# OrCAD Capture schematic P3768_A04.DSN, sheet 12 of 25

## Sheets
12 0013_USB Type C: size Custom
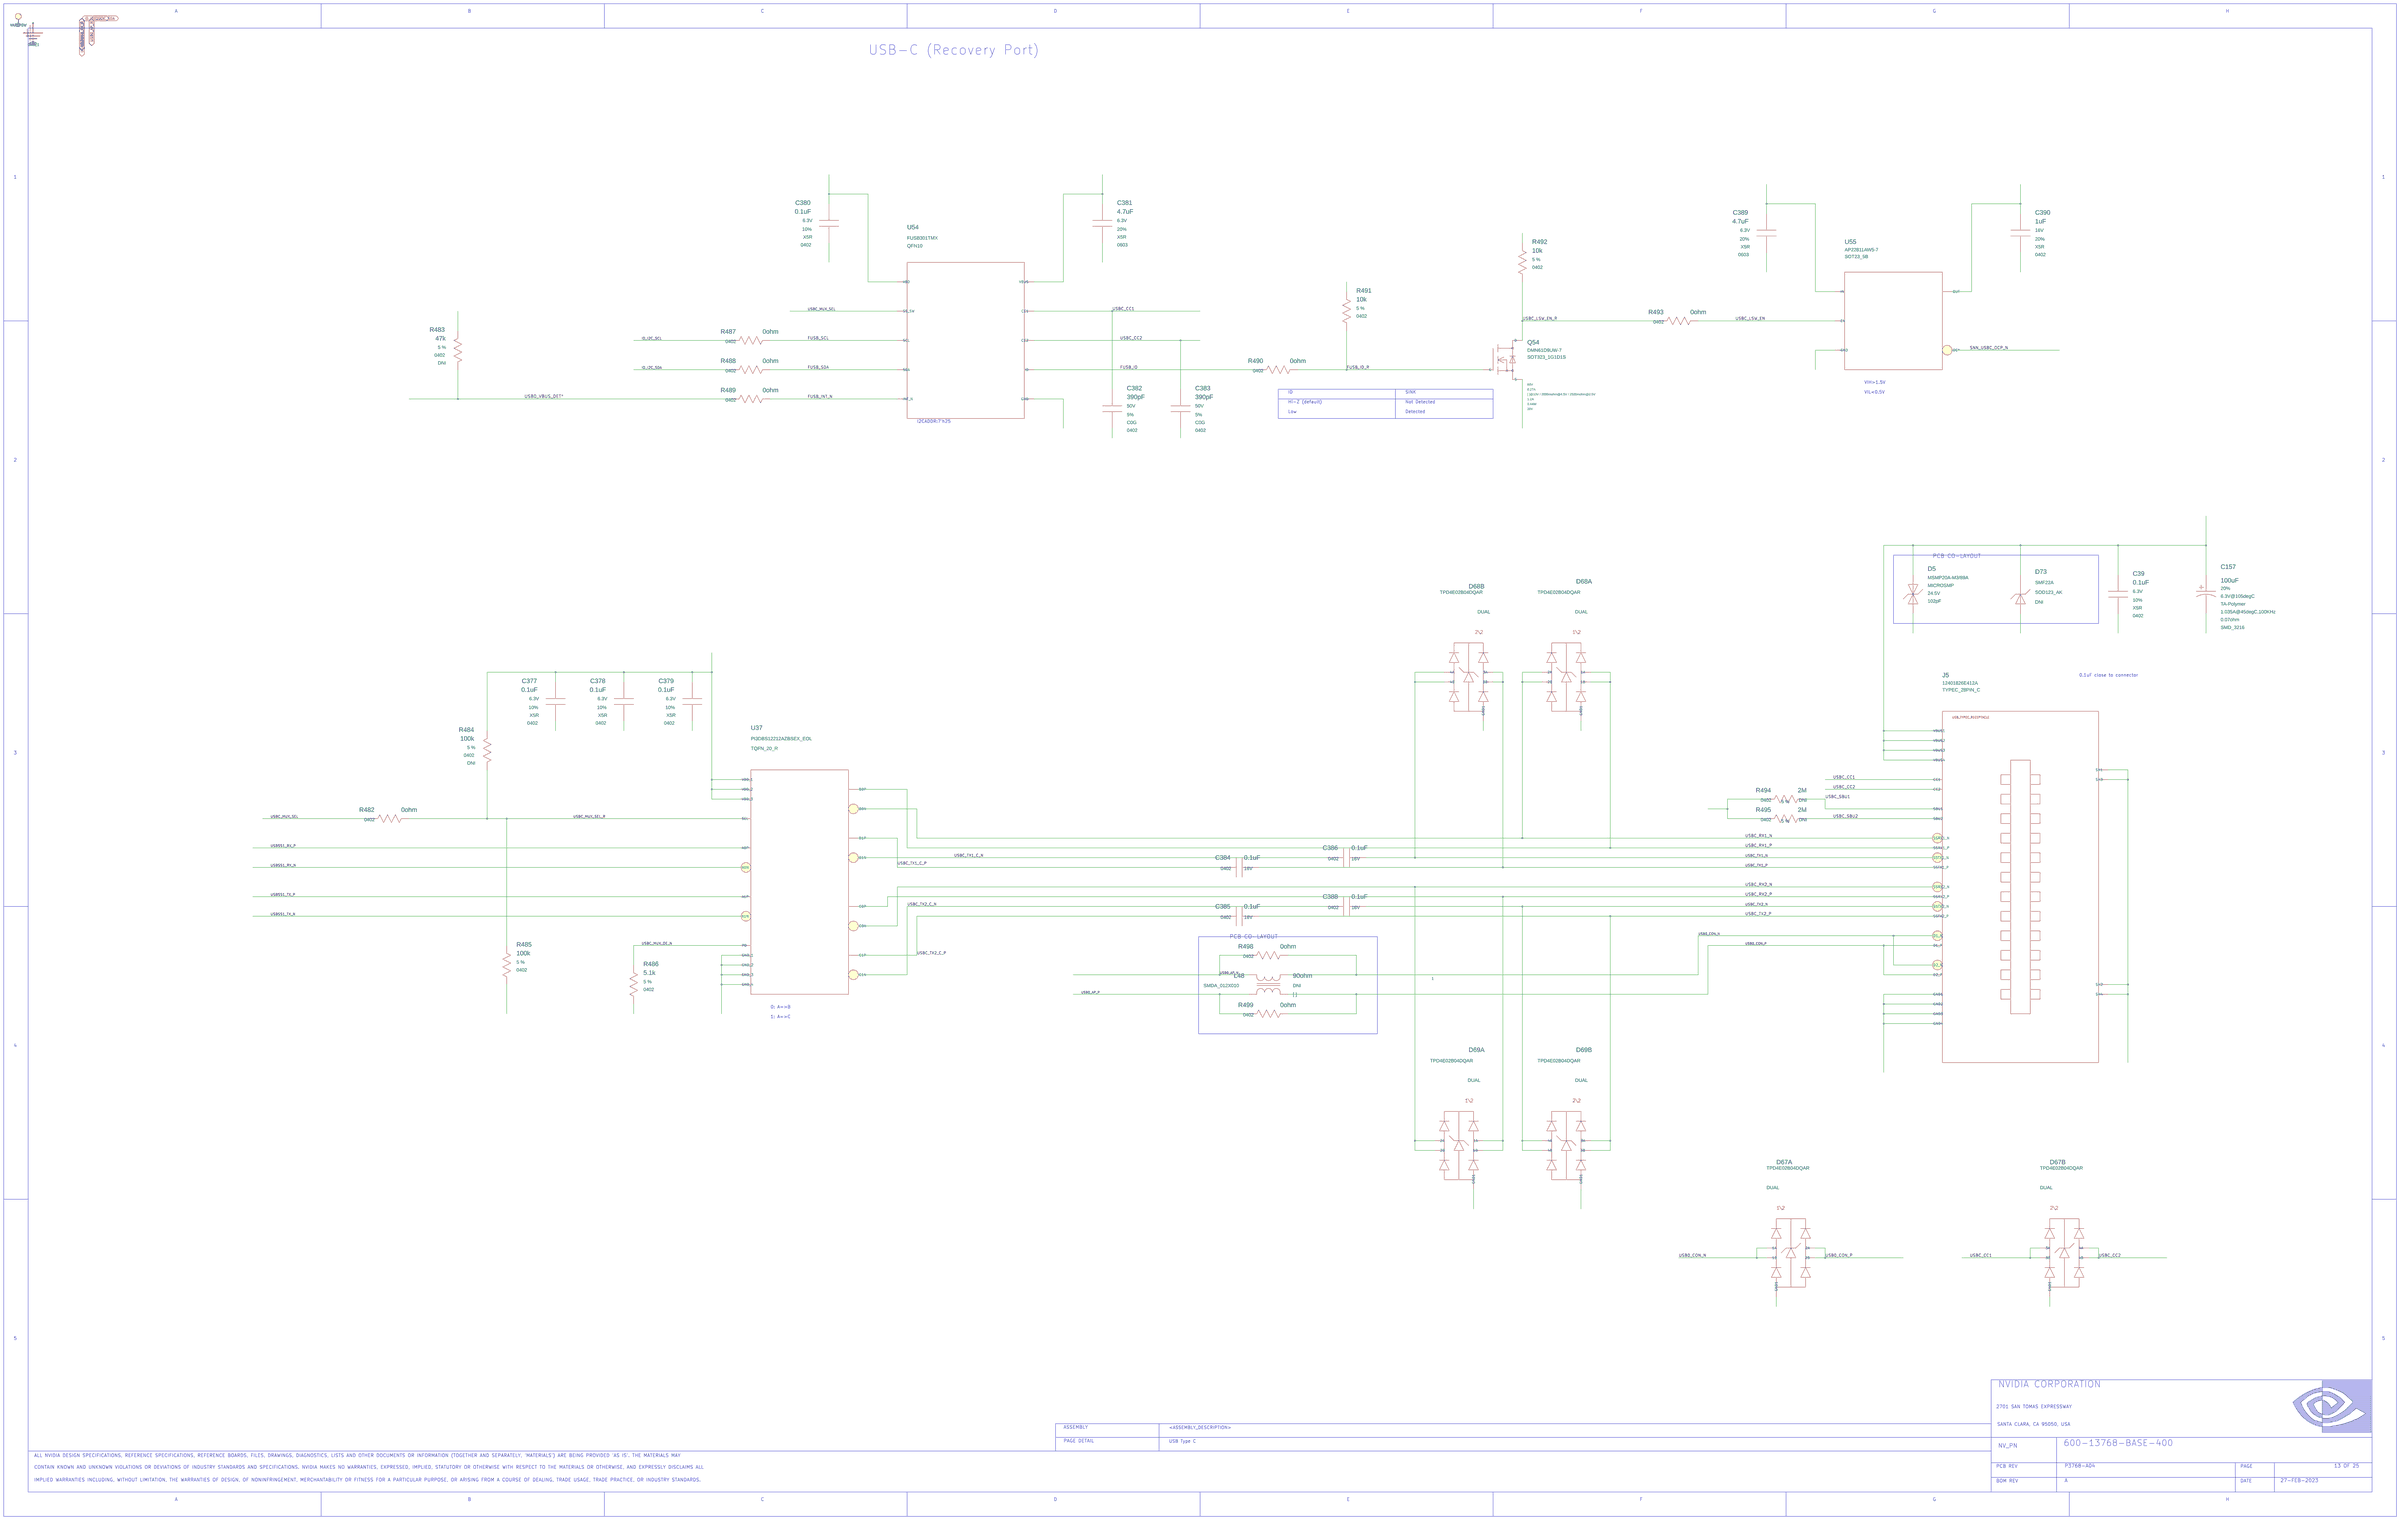
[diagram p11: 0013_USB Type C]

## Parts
C39  0.1uF  [0402]
C157  100uF  [CAP_SMD_3216]
C377  0.1uF  [0402]
C378  0.1uF  [0402]
C379  0.1uF  [0402]
C380  0.1uF  [0402]
C381  4.7uF  [0603]
C382  390pF  [0402]
C383  390pF  [0402]
C384  0.1uF  [0402]
C385  0.1uF  [0402]
C386  0.1uF  [0402]
C388  0.1uF  [0402]
C389  4.7uF  [0603]
C390  1uF  [0402]
D5  D_ESD  [DIODE_SMD_025X013]
D67  D_ESD_DIFFPAIR  [TSLP10_P050_025X010]  (sections A,B)
D68  D_ESD_DIFFPAIR  [TSLP10_P050_025X010]  (sections A,B)
D69  D_ESD_DIFFPAIR  [TSLP10_P050_025X010]  (sections A,B)
D73  D_ESD  [DIODE_SMD_SOD123_B_AKP]
J5  CON_USB3  [CON_USB_024_SMT_RA_F_100X096_C]
L48  90ohm  [IND_NONRKO_SMD_012X010]
Q54  Q_FET_N_ENH  [SOT323]
R482  0ohm  [0402]
R483  47k  [0402]
R484  100k  [0402]
R485  100k  [0402]
R486  5.1k  [0402]
R487  0ohm  [0402]
R488  0ohm  [0402]
R489  0ohm  [0402]
R490  0ohm  [0402]
R491  10k  [0402]
R492  10k  [0402]
R493  0ohm  [0402]
R494  2M  [0402]
R495  2M  [0402]
R498  0ohm  [0402]
R499  0ohm  [0402]
U37  U_MUX_PCIE  [MULTI_QFN020R_P050_0025X0045_T010X030]
U54  U_USB_FUSB301  [QFN010R_P040_0012X0016_B]
U55  U_SW_LOAD  [SOT23_5_B]

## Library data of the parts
C39 = C#1: ASSEMBLY: USBC; CDS_LIB: discrete; CDS_PART_NAME: C_0402-0.1UF,X5R,10%,6.3V,039-0007-000; CDS_PHYS_PART_NAME: C_0402-0.1UF,X5R,10%,6.3V,039-0007-000-0.1UF,039-0007-000; CDS_SEC: 1; CHIPS_PART_NAME: C; DEVICE_TYPENAME: C_0402-01UFX5R1063V039-0007-000-01UF039-0007-000; DRAWING: @P3768_A04_LIB.P3768_A04(SCH_1):PAGE13; MAT: X5R; MAX_VOLTAGE: 6.3V; NV_PN: 039-0007-000; PATH: I449; PHYS_PAGE: 13; ROT: 0; SEC: 1; SIGNAL_MODEL: nv_cap; TOL: 10%; VER: 1; XY: (-1300,4600)
C157 = C_POL: ASSEMBLY: USBC; CDS_LIB: discrete; CDS_PART_NAME: C_POL_SMD_3216-100UF,TA-POLYMER,20%,6.3V@105DEGC,0.07OHM,9.999UH,1.035A@45DEGC,100KHZ,032-0637-000; CDS_PHYS_PART_NAME: C_POL_SMD_3216-100UF,TA-POLYMER,20%,6.3V@105DEGC,0.07OHM,9.999UH,1.035A@45DEGC,100KHZ,032-0637-000-032-0637-000,100UF; CDS_SEC: 1; DEVICE_TYPENAME: C_POL_SMD_3216-100UFTA-POLYMER2063V105DEGC007OHM9999UH1035A45DEGC100KHZ032-0637-000-032-0637-000100UF; DRAWING: @P3768_A04_LIB.P3768_A04(SCH_1):PAGE13; ESL: 9.999uH; ESR: 0.07ohm; MAT: TA-Polymer; MAX_VOLTAGE: 6.3V@105degC; NV_PN: 032-0637-000; PACK_TYPE: SMD_3216; PATH: I467; PHYS_PAGE: 13; RIPPLE_CURRENT: 1.035A@45degC,100KHz; ROT: 0; SEC: 1; SIGNAL_MODEL: nv_capp; TOL: 20%; VER: 1; XY: (-850,4600)
C377 = C#1: ASSEMBLY: USBC; CDS_LIB: discrete; CDS_PART_NAME: C_0402-0.1UF,X5R,10%,6.3V,039-0007-000; CDS_PHYS_PART_NAME: C_0402-0.1UF,X5R,10%,6.3V,039-0007-000-0.1UF,039-0007-000; CDS_SEC: 1; CHIPS_PART_NAME: C; DEVICE_TYPENAME: C_0402-01UFX5R1063V039-0007-000-01UF039-0007-000; DRAWING: @P3768_A04_LIB.P3768_A04(SCH_1):PAGE13; MAT: X5R; MAX_VOLTAGE: 6.3V; NV_PN: 039-0007-000; PATH: I448; PHYS_PAGE: 13; ROT: 2; SEC: 1; SIGNAL_MODEL: nv_cap; TOL: 10%; VER: 1; XY: (-9300,4050)
C378 = C#1: ASSEMBLY: USBC; CDS_LIB: discrete; CDS_PART_NAME: C_0402-0.1UF,X5R,10%,6.3V,039-0007-000; CDS_PHYS_PART_NAME: C_0402-0.1UF,X5R,10%,6.3V,039-0007-000-0.1UF,039-0007-000; CDS_SEC: 1; CHIPS_PART_NAME: C; DEVICE_TYPENAME: C_0402-01UFX5R1063V039-0007-000-01UF039-0007-000; DRAWING: @P3768_A04_LIB.P3768_A04(SCH_1):PAGE13; MAT: X5R; MAX_VOLTAGE: 6.3V; NV_PN: 039-0007-000; PATH: I447; PHYS_PAGE: 13; ROT: 2; SEC: 1; SIGNAL_MODEL: nv_cap; TOL: 10%; VER: 1; XY: (-8950,4050)
C379 = C#1: ASSEMBLY: USBC; CDS_LIB: discrete; CDS_PART_NAME: C_0402-0.1UF,X5R,10%,6.3V,039-0007-000; CDS_PHYS_PART_NAME: C_0402-0.1UF,X5R,10%,6.3V,039-0007-000-0.1UF,039-0007-000; CDS_SEC: 1; CHIPS_PART_NAME: C; DEVICE_TYPENAME: C_0402-01UFX5R1063V039-0007-000-01UF039-0007-000; DRAWING: @P3768_A04_LIB.P3768_A04(SCH_1):PAGE13; MAT: X5R; MAX_VOLTAGE: 6.3V; NV_PN: 039-0007-000; PATH: I443; PHYS_PAGE: 13; ROT: 2; SEC: 1; SIGNAL_MODEL: nv_cap; TOL: 10%; VER: 1; XY: (-8600,4050)
C380 = C#1: ASSEMBLY: USBC; CDS_LIB: discrete; CDS_PART_NAME: C_0402-0.1UF,X5R,10%,6.3V,039-0007-000; CDS_PHYS_PART_NAME: C_0402-0.1UF,X5R,10%,6.3V,039-0007-000-0.1UF,039-0007-000; CDS_SEC: 1; CHIPS_PART_NAME: C; DEVICE_TYPENAME: C_0402-01UFX5R1063V039-0007-000-01UF039-0007-000; DRAWING: @P3768_A04_LIB.P3768_A04(SCH_1):PAGE13; MAT: X5R; MAX_VOLTAGE: 6.3V; NV_PN: 039-0007-000; PATH: I444; PHYS_PAGE: 13; ROT: 2; SEC: 1; SIGNAL_MODEL: nv_cap; TOL: 10%; VER: 1; XY: (-7900,6500)
C381 = C#1: ASSEMBLY: USBC; CDS_LIB: discrete; CDS_PART_NAME: C_0603-4.7UF,X5R,20%,6.3V,032-2124-000; CDS_PHYS_PART_NAME: C_0603-4.7UF,X5R,20%,6.3V,032-2124-000-032-2124-000,4.7UF; CDS_SEC: 1; CHIPS_PART_NAME: C; DEVICE_TYPENAME: C_0603-47UFX5R2063V032-2124-000-032-2124-00047UF; DRAWING: @P3768_A04_LIB.P3768_A04(SCH_1):PAGE13; MAT: X5R; MAX_VOLTAGE: 6.3V; NV_PN: 032-2124-000; PATH: I435; PHYS_PAGE: 13; ROT: 0; SEC: 1; SIGNAL_MODEL: nv_cap; TOL: 20%; VER: 1; XY: (-6500,6500)
C382 = C#1: ASSEMBLY: USBC; CDS_LIB: discrete; CDS_PART_NAME: C_0402-390PF,C0G,5%,50V,035-0293-000; CDS_PHYS_PART_NAME: C_0402-390PF,C0G,5%,50V,035-0293-000-035-0293-000,390PF; CDS_SEC: 1; CHIPS_PART_NAME: C; DEVICE_TYPENAME: C_0402-390PFC0G550V035-0293-000-035-0293-000390PF; DRAWING: @P3768_A04_LIB.P3768_A04(SCH_1):PAGE13; MAT: C0G; MAX_VOLTAGE: 50V; NV_PN: 035-0293-000; PATH: I410; PHYS_PAGE: 13; PSPICETEMPLATE: X^@REFDES  %1    %2   @NV_PN; ROT: 0; SEC: 1; SIGNAL_MODEL: nv_cap; TOL: 5%; VER: 1; XY: (-6450,5550)
C383 = C#1: ASSEMBLY: USBC; CDS_LIB: discrete; CDS_PART_NAME: C_0402-390PF,C0G,5%,50V,035-0293-000; CDS_PHYS_PART_NAME: C_0402-390PF,C0G,5%,50V,035-0293-000-035-0293-000,390PF; CDS_SEC: 1; CHIPS_PART_NAME: C; DEVICE_TYPENAME: C_0402-390PFC0G550V035-0293-000-035-0293-000390PF; DRAWING: @P3768_A04_LIB.P3768_A04(SCH_1):PAGE13; MAT: C0G; MAX_VOLTAGE: 50V; NV_PN: 035-0293-000; PATH: I414; PHYS_PAGE: 13; PSPICETEMPLATE: X^@REFDES  %1    %2   @NV_PN; ROT: 0; SEC: 1; SIGNAL_MODEL: nv_cap; TOL: 5%; VER: 1; XY: (-6100,5550)
C384 = C: ASSEMBLY: USBC; CDS_LIB: discrete; CDS_PART_NAME: C_0402-0.1UF,X7R,10%,16V,032-0793-000; CDS_PHYS_PART_NAME: C_0402-0.1UF,X7R,10%,16V,032-0793-000-0.1UF,032-0793-000; CDS_SEC: 1; DEVICE_TYPENAME: C_0402-01UFX7R1016V032-0793-000-01UF032-0793-000; DRAWING: @P3768_A04_LIB.P3768_A04(SCH_1):PAGE13; MAT: X7R; MAX_VOLTAGE: 16V; NV_PN: 032-0793-000; PATH: I398; PHYS_PAGE: 13; PSPICETEMPLATE: X^@REFDES  %1    %2   @NV_PN; ROT: 0; SEC: 1; SIGNAL_MODEL: nv_cap; TOL: 10%; VER: 2; XY: (-5800,3200)
C385 = C: ASSEMBLY: USBC; CDS_LIB: discrete; CDS_PART_NAME: C_0402-0.1UF,X7R,10%,16V,032-0793-000; CDS_PHYS_PART_NAME: C_0402-0.1UF,X7R,10%,16V,032-0793-000-0.1UF,032-0793-000; CDS_SEC: 1; DEVICE_TYPENAME: C_0402-01UFX7R1016V032-0793-000-01UF032-0793-000; DRAWING: @P3768_A04_LIB.P3768_A04(SCH_1):PAGE13; MAT: X7R; MAX_VOLTAGE: 16V; NV_PN: 032-0793-000; PATH: I400; PHYS_PAGE: 13; PSPICETEMPLATE: X^@REFDES  %1    %2   @NV_PN; ROT: 0; SEC: 1; SIGNAL_MODEL: nv_cap; TOL: 10%; VER: 2; XY: (-5800,2950)
C386 = C: ASSEMBLY: USBC; CDS_LIB: discrete; CDS_PART_NAME: C_0402-0.1UF,X7R,10%,16V,032-0793-000; CDS_PHYS_PART_NAME: C_0402-0.1UF,X7R,10%,16V,032-0793-000-0.1UF,032-0793-000; CDS_SEC: 1; DEVICE_TYPENAME: C_0402-01UFX7R1016V032-0793-000-01UF032-0793-000; DRAWING: @P3768_A04_LIB.P3768_A04(SCH_1):PAGE13; MAT: X7R; MAX_VOLTAGE: 16V; NV_PN: 032-0793-000; PATH: I399; PHYS_PAGE: 13; PSPICETEMPLATE: X^@REFDES  %1    %2   @NV_PN; ROT: 0; SEC: 1; SIGNAL_MODEL: nv_cap; TOL: 10%; VER: 2; XY: (-5250,3250)
C388 = C: ASSEMBLY: USBC; CDS_LIB: discrete; CDS_PART_NAME: C_0402-0.1UF,X7R,10%,16V,032-0793-000; CDS_PHYS_PART_NAME: C_0402-0.1UF,X7R,10%,16V,032-0793-000-0.1UF,032-0793-000; CDS_SEC: 1; DEVICE_TYPENAME: C_0402-01UFX7R1016V032-0793-000-01UF032-0793-000; DRAWING: @P3768_A04_LIB.P3768_A04(SCH_1):PAGE13; MAT: X7R; MAX_VOLTAGE: 16V; NV_PN: 032-0793-000; PATH: I401; PHYS_PAGE: 13; PSPICETEMPLATE: X^@REFDES  %1    %2   @NV_PN; ROT: 0; SEC: 1; SIGNAL_MODEL: nv_cap; TOL: 10%; VER: 2; XY: (-5250,3000)
C389 = C#1: ASSEMBLY: USBC; CDS_LIB: discrete; CDS_PART_NAME: C_0603-4.7UF,X5R,20%,6.3V,032-2124-000; CDS_PHYS_PART_NAME: C_0603-4.7UF,X5R,20%,6.3V,032-2124-000-032-2124-000,4.7UF; CDS_SEC: 1; CHIPS_PART_NAME: C; DEVICE_TYPENAME: C_0603-47UFX5R2063V032-2124-000-032-2124-00047UF; DRAWING: @P3768_A04_LIB.P3768_A04(SCH_1):PAGE13; MAT: X5R; MAX_VOLTAGE: 6.3V; NV_PN: 032-2124-000; PATH: I438; PHYS_PAGE: 13; ROT: 2; SEC: 1; SIGNAL_MODEL: nv_cap; TOL: 20%; VER: 1; XY: (-3100,6450)
C390 = C#1: ASSEMBLY: USBC; CDS_LIB: discrete; CDS_PART_NAME: C_0402-1UF,X5R,20%,16V,032-0521-000; CDS_PHYS_PART_NAME: C_0402-1UF,X5R,20%,16V,032-0521-000-032-0521-000,1UF; CDS_SEC: 1; CHIPS_PART_NAME: C; DEVICE_TYPENAME: C_0402-1UFX5R2016V032-0521-000-032-0521-0001UF; DRAWING: @P3768_A04_LIB.P3768_A04(SCH_1):PAGE13; MAT: X5R; MAX_VOLTAGE: 16V; NV_PN: 032-0521-000; PATH: I432; PHYS_PAGE: 13; PSPICETEMPLATE: X^@REFDES  %1    %2   @NV_PN; ROT: 0; SEC: 1; SIGNAL_MODEL: nv_cap; TOL: 20%; VER: 1; XY: (-1800,6450)
D5 = D_ESD: ASSEMBLY: USBC; BREAKDOWN_VOLTAGE_MIN_TYP: 22.2V; CAPACITANCE_MAX_TYP: 102pF; CDS_LIB: discrete; CDS_PART_NAME: D_ESD_MICROSMP-MSMP20A-M3/89A,1 LINE,UNI-DIRECTIONAL,24.5V,1UA,22.2V,42.8V@23.4A,102PF,090-0378-000; CDS_PHYS_PART_NAME: D_ESD_MICROSMP-MSMP20A-M3/89A,1 LINE,UNI-DIRECTIONAL,24.5V,1UA,22.2V,42.8V@23.4A,102PF,090-0378-000-090-0378-000; CDS_SEC: 1; CLAMPING_VOLTAGE: 42.8V@23.4A; CONFIGURATION: 1 Line; DEVICE_TYPENAME: D_ESD_MICROSMP-MSMP20A-M389A1LINEUNI-DIRECTIONAL245V1UA222V428V234A102PF090-0378-000-090-0378-000; DRAWING: @P3768_A04_LIB.P3768_A04(SCH_1):PAGE13; MAX_REVERSE_LEAKAGE_CURRENT: 1uA; MAX_REVERSE_VOLTAGE: 24.5V; NV_NAME: MSMP20A-M3/89A; NV_PN: 090-0378-000; PACK_TYPE: MICROSMP; PATH: I381; PHYS_PAGE: 13; POLARITY: Uni-Directional; ROT: 0; SEC: 1; VER: 2; XY: (-2350,4600)
D67 = D_ESD_DIFFPAIR: ASSEMBLY: USBC; BREAKDOWN_VOLTAGE_MIN_TYP: 6.7V; CAPACITANCE_MAX_TYP: 0.37pF; CDS_LIB: discrete; CDS_PART_NAME: D_ESD_DIFFPAIR_DUAL-TPD4E02B04DQAR,2 DIFFPAIR,BI-DIRECTIONAL,6V,0.01UA,6.7V,8V@40A,0.37PF,090-0296-000; CDS_PHYS_PART_NAME: D_ESD_DIFFPAIR_DUAL-TPD4E02B04DQAR,2 DIFFPAIR,BI-DIRECTIONAL,6V,0.01UA,6.7V,8V@40A,0.37PF,090-0296-000-090-0296-000; CDS_SEC: 1; CLAMPING_VOLTAGE: 8V@40A; CONFIGURATION: 2 Diffpair; CaptureCellPackProp: D_ESD_DIFFPAIRA; DEVICE_TYPENAME: D_ESD_DIFFPAIR_DUAL-TPD4E02B04DQAR2DIFFPAIRBI-DIRECTIONAL6V001UA67V8V40A037PF090-0296-000-090-0296-000; DRAWING: @P3768_A04_LIB.P3768_A04(SCH_1):PAGE13; MAX_REVERSE_LEAKAGE_CURRENT: 0.01uA; MAX_REVERSE_VOLTAGE: 6V; NV_NAME: TPD4E02B04DQAR; NV_PN: 090-0296-000; PACK_TYPE: DUAL; PATH: I392; PHYS_PAGE: 13; POLARITY: Bi-Directional; ROT: 0; SEC: 1; VER: 1; XY: (-3000,1250)
D68 = D_ESD_DIFFPAIR: ASSEMBLY: USBC; BREAKDOWN_VOLTAGE_MIN_TYP: 6.7V; CAPACITANCE_MAX_TYP: 0.37pF; CDS_LIB: discrete; CDS_PART_NAME: D_ESD_DIFFPAIR_DUAL-TPD4E02B04DQAR,2 DIFFPAIR,BI-DIRECTIONAL,6V,0.01UA,6.7V,8V@40A,0.37PF,090-0296-000; CDS_PHYS_PART_NAME: D_ESD_DIFFPAIR_DUAL-TPD4E02B04DQAR,2 DIFFPAIR,BI-DIRECTIONAL,6V,0.01UA,6.7V,8V@40A,0.37PF,090-0296-000-090-0296-000; CDS_SEC: 2; CLAMPING_VOLTAGE: 8V@40A; CONFIGURATION: 2 Diffpair; CaptureCellPackProp: D_ESD_DIFFPAIRB; DEVICE_TYPENAME: D_ESD_DIFFPAIR_DUAL-TPD4E02B04DQAR2DIFFPAIRBI-DIRECTIONAL6V001UA67V8V40A037PF090-0296-000-090-0296-000; DRAWING: @P3768_A04_LIB.P3768_A04(SCH_1):PAGE13; MAX_REVERSE_LEAKAGE_CURRENT: 0.01uA; MAX_REVERSE_VOLTAGE: 6V; NV_NAME: TPD4E02B04DQAR; NV_PN: 090-0296-000; PACK_TYPE: DUAL; PATH: I371; PHYS_PAGE: 13; POLARITY: Bi-Directional; ROT: 2; SEC: 2; VER: 2; XY: (-4600,4200)
D69 = D_ESD_DIFFPAIR: ASSEMBLY: USBC; BREAKDOWN_VOLTAGE_MIN_TYP: 6.7V; CAPACITANCE_MAX_TYP: 0.37pF; CDS_LIB: discrete; CDS_PART_NAME: D_ESD_DIFFPAIR_DUAL-TPD4E02B04DQAR,2 DIFFPAIR,BI-DIRECTIONAL,6V,0.01UA,6.7V,8V@40A,0.37PF,090-0296-000; CDS_PHYS_PART_NAME: D_ESD_DIFFPAIR_DUAL-TPD4E02B04DQAR,2 DIFFPAIR,BI-DIRECTIONAL,6V,0.01UA,6.7V,8V@40A,0.37PF,090-0296-000-090-0296-000; CDS_SEC: 1; CLAMPING_VOLTAGE: 8V@40A; CONFIGURATION: 2 Diffpair; CaptureCellPackProp: D_ESD_DIFFPAIRA; DEVICE_TYPENAME: D_ESD_DIFFPAIR_DUAL-TPD4E02B04DQAR2DIFFPAIRBI-DIRECTIONAL6V001UA67V8V40A037PF090-0296-000-090-0296-000; DRAWING: @P3768_A04_LIB.P3768_A04(SCH_1):PAGE13; MAX_REVERSE_LEAKAGE_CURRENT: 0.01uA; MAX_REVERSE_VOLTAGE: 6V; NV_NAME: TPD4E02B04DQAR; NV_PN: 090-0296-000; PACK_TYPE: DUAL; PATH: I365; PHYS_PAGE: 13; POLARITY: Bi-Directional; ROT: 2; SEC: 1; VER: 1; XY: (-4650,1800)
D73 = D_ESD#1: ASSEMBLY: USBC; BREAKDOWN_VOLTAGE_MIN_TYP: 24.4V; CAPACITANCE_MAX_TYP: 80pF; CDS_LIB: discrete; CDS_PART_NAME: D_ESD_SOD123_AK-SMF22A,1 LINE,UNI-DIRECTIONAL,22V,1UA,24.4V,35.5V@5.6A,80PF,090-0450-000; CDS_PHYS_PART_NAME: D_ESD_SOD123_AK-SMF22A,1 LINE,UNI-DIRECTIONAL,22V,1UA,24.4V,35.5V@5.6A,80PF,090-0450-000-090-0450-000; CDS_SEC: 1; CLAMPING_VOLTAGE: 35.5V@5.6A; CONFIGURATION: 1 Line; DEVICE_TYPENAME: D_ESD_SOD123_AK-SMF22A1LINEUNI-DIRECTIONAL22V1UA244V355V56A80PF090-0450-000-090-0450-000; DRAWING: @P3768_A04_LIB.P3768_A04(SCH_1):PAGE13; MAX_REVERSE_LEAKAGE_CURRENT: 1uA; MAX_REVERSE_VOLTAGE: 22V; NV_NAME: SMF22A; NV_PN: 090-0450-000; PACK_TYPE: SOD123_AK; PATH: I376; PHYS_PAGE: 13; POLARITY: Uni-Directional; ROT: 0; SEC: 1; SKU: DNI; VER: 5; XY: (-1800,4600)
J5 = CON_USB3: ANGLE: 90; ASSEMBLY: USBC; CDS_LIB: electro_mechanic; CDS_PART_NAME: CON_USB3_TYPEC_28PIN_C-12401826E412A,RECEPTACLE,0.5MM,90,YES,YES,YES,YES,YES,500 V,6 A,080-1890-000; CDS_PHYS_PART_NAME: CON_USB3_TYPEC_28PIN_C-12401826E412A,RECEPTACLE,0.5MM,90,YES,YES,YES,YES,YES,500 V,6 A,080-1890-000-080-1890-000; CDS_SEC: 1; DEVICE_TYPENAME: CON_USB3_TYPEC_28PIN_C-12401826E412ARECEPTACLE05MM90YESYESYESYESYES500V6A080-1890-000-080-1890-000; DRAWING: @P3768_A04_LIB.P3768_A04(SCH_1):PAGE13; EMI_GROUND_TAB: YES; GENDER: RECEPTACLE; LATCHING: YES; MAX_CURRENT: 6 A; MAX_VOLTAGE: 500 V; NV_NAME: 12401826E412A; NV_PN: 080-1890-000; PACK_TYPE: TYPEC_28PIN_C; PATH: I463; PHYS_PAGE: 13; PITCH: 0.5mm; REFLOW: YES; ROT: 0; SEC: 1; SHIELDED: YES; SHROUDED: YES; VER: 16; XY: (-1800,3100)
L48 = L_CMF_4P: ASSEMBLY: USB3_TYPEA; CDS_LIB: discrete; CDS_PART_NAME: L_CMF_4P_SMDA_012X010-90OHM,[ ],25%,0.2A,0.4OHM,[ ],102-0037-000; CDS_PHYS_PART_NAME: L_CMF_4P_SMDA_012X010-90OHM,[ ],25%,0.2A,0.4OHM,[ ],102-0037-000-102-0037-000,90OHM; CDS_SEC: 1; DC_RESISTANCE: 0.4ohm; DEVICE_TYPENAME: L_CMF_4P_SMDA_012X010-90OHM2502A04OHM102-0037-000-102-0037-00090OHM; DRAWING: @P3768_A04_LIB.P3768_A04(SCH_1):PAGE13; MAT: [ ]; MAX_CURRENT: 0.2A; NO_XNET_CONNECTION: 1; NV_NAME: [ ]; NV_PN: 102-0037-000; PACK_TYPE: SMDA_012X010; PATH: I462; PHYS_PAGE: 13; PLACEMENT_NOTE: CoLayout with R167, R169; ROT: 0; SEC: 1; SIGNAL_MODEL: nv_ind_cmf_4p; SKU: DNI; TOL: 25%; VER: 1; XY: (-5650,2600)
Q54 = Q_FET_N_ENH#1: ASSEMBLY: USBC; CDS_LIB: discrete; CDS_PART_NAME: Q_FET_N_ENH_SOT323_1G1D1S-DMN61D9UW-7,60V,[ ]@10V / 2000MOHM@4.5V / 2500MOHM@2.5V,0.27A,1.2A,20V,0.44W,[ ]@10V / 0.4NC@4.5V / [ ]@2.5V,300-1185-000; CDS_PHYS_PART_NAME: Q_FET_N_ENH_SOT323_1G1D1S-DMN61D9UW-7,60V,[ ]@10V / 2000MOHM@4.5V / 2500MOHM@2.5V,0.27A,1.2A,20V,0.44W,[ ]@10V / 0.4NC@4.5V / B; CDS_SEC: 1; CONTINUOUS_CURRENT: 0.27A; CaptureCellPackProp: Q_FET_N_ENH##1; DEVICE_TYPENAME: Q_FET_N_ENH_SOT323_1G1D1S-DMN61D9UW-760V10V2000MOHM45V2500MOHM25V027A12A20V044W10V04NC45VB; DRAWING: @P3768_A04_LIB.P3768_A04(SCH_1):PAGE13; MAX_CURRENT: 1.2A; MAX_VOLTAGE: 60V; MAX_WATTAGE: 0.44W; NV_NAME: DMN61D9UW-7; NV_PN: 300-1185-000; PACK_TYPE: SOT323_1G1D1S; PATH: I466; PHYS_PAGE: 13; Q_G: [ ]@10V / 0.4nC@4.5V / [ ]@2.5V; ROT: 0; R_DS_ON: [ ]@10V / 2000mohm@4.5V / 2500mohm@2.5V; SEC: 1; VER: 2; V_BE_GS: 20V; XY: (-4450,5800)
R482 = R#1: ASSEMBLY: USBC; CDS_LIB: discrete; CDS_PART_NAME: R_0402-0OHM,0.05 OHM,62.5MW,195-2655-000; CDS_PHYS_PART_NAME: R_0402-0OHM,0.05 OHM,62.5MW,195-2655-000-0OHM,195-2655-000; CDS_SEC: 1; CHIPS_PART_NAME: R; DEVICE_TYPENAME: R_0402-0OHM005OHM625MW195-2655-000-0OHM195-2655-000; DRAWING: @P3768_A04_LIB.P3768_A04(SCH_1):PAGE13; MAX_WATTAGE: 62.5mW; NV_PN: 195-2655-000; PATH: I415; PHYS_PAGE: 13; ROT: 0; SEC: 1; SIGNAL_MODEL: nv_res; TOL: 0.05 ohm; VER: 1; XY: (-10150,3450)
R483 = R: ASSEMBLY: USBC; CDS_LIB: discrete; CDS_PART_NAME: R_0402-47K,5 %,62.5MW,195-0599-000; CDS_PHYS_PART_NAME: R_0402-47K,5 %,62.5MW,195-0599-000-195-0599-000,47K; CDS_SEC: 1; DEVICE_TYPENAME: R_0402-47K5625MW195-0599-000-195-0599-00047K; DRAWING: @P3768_A04_LIB.P3768_A04(SCH_1):PAGE13; MAX_WATTAGE: 62.5mW; NV_PN: 195-0599-000; PATH: I439; PHYS_PAGE: 13; ROT: 2; SEC: 1; SIGNAL_MODEL: nv_res; SKU: DNI; TOL: 5 %; VER: 2; XY: (-9800,5850)
R484 = R: ASSEMBLY: USBC; CDS_LIB: discrete; CDS_PART_NAME: R_0402-100K,5 %,62.5MW,195-0487-000; CDS_PHYS_PART_NAME: R_0402-100K,5 %,62.5MW,195-0487-000-100K,195-0487-000; CDS_SEC: 1; DEVICE_TYPENAME: R_0402-100K5625MW195-0487-000-100K195-0487-000; DRAWING: @P3768_A04_LIB.P3768_A04(SCH_1):PAGE13; MAX_WATTAGE: 62.5mW; NV_PN: 195-0487-000; PATH: I388; PHYS_PAGE: 13; PSPICETEMPLATE: X^@REFDES  %1    %2   @NV_PN; ROT: 2; SEC: 1; SIGNAL_MODEL: nv_res; SKU: DNI; TOL: 5 %; VER: 2; XY: (-9650,3800)
R485 = R: ASSEMBLY: USBC; CDS_LIB: discrete; CDS_PART_NAME: R_0402-100K,5 %,62.5MW,195-0487-000; CDS_PHYS_PART_NAME: R_0402-100K,5 %,62.5MW,195-0487-000-100K,195-0487-000; CDS_SEC: 1; DEVICE_TYPENAME: R_0402-100K5625MW195-0487-000-100K195-0487-000; DRAWING: @P3768_A04_LIB.P3768_A04(SCH_1):PAGE13; MAX_WATTAGE: 62.5mW; NV_PN: 195-0487-000; PATH: I387; PHYS_PAGE: 13; PSPICETEMPLATE: X^@REFDES  %1    %2   @NV_PN; ROT: 0; SEC: 1; SIGNAL_MODEL: nv_res; TOL: 5 %; VER: 2; XY: (-9550,2700)
R486 = R: ASSEMBLY: USBC; CDS_LIB: discrete; CDS_PART_NAME: R_0402-5.1K,5 %,62.5MW,195-0605-000; CDS_PHYS_PART_NAME: R_0402-5.1K,5 %,62.5MW,195-0605-000-195-0605-000,5.1K; CDS_SEC: 1; DEVICE_TYPENAME: R_0402-51K5625MW195-0605-000-195-0605-00051K; DRAWING: @P3768_A04_LIB.P3768_A04(SCH_1):PAGE13; MAX_WATTAGE: 62.5mW; NV_PN: 195-0605-000; PATH: I386; PHYS_PAGE: 13; PSPICETEMPLATE: X^@REFDES  %1    %2   @NV_PN; ROT: 0; SEC: 1; SIGNAL_MODEL: nv_res; TOL: 5 %; VER: 2; XY: (-8900,2600)
R487 = R#1: ASSEMBLY: USBC; CDS_LIB: discrete; CDS_PART_NAME: R_0402-0OHM,0.05 OHM,62.5MW,195-2655-000; CDS_PHYS_PART_NAME: R_0402-0OHM,0.05 OHM,62.5MW,195-2655-000-0OHM,195-2655-000; CDS_SEC: 1; CHIPS_PART_NAME: R; DEVICE_TYPENAME: R_0402-0OHM005OHM625MW195-2655-000-0OHM195-2655-000; DRAWING: @P3768_A04_LIB.P3768_A04(SCH_1):PAGE13; MAX_WATTAGE: 62.5mW; NV_PN: 195-2655-000; PATH: I418; PHYS_PAGE: 13; ROT: 0; SEC: 1; SIGNAL_MODEL: nv_res; TOL: 0.05 ohm; VER: 1; XY: (-8300,5900)
R488 = R#1: ASSEMBLY: USBC; CDS_LIB: discrete; CDS_PART_NAME: R_0402-0OHM,0.05 OHM,62.5MW,195-2655-000; CDS_PHYS_PART_NAME: R_0402-0OHM,0.05 OHM,62.5MW,195-2655-000-0OHM,195-2655-000; CDS_SEC: 1; CHIPS_PART_NAME: R; DEVICE_TYPENAME: R_0402-0OHM005OHM625MW195-2655-000-0OHM195-2655-000; DRAWING: @P3768_A04_LIB.P3768_A04(SCH_1):PAGE13; MAX_WATTAGE: 62.5mW; NV_PN: 195-2655-000; PATH: I417; PHYS_PAGE: 13; ROT: 0; SEC: 1; SIGNAL_MODEL: nv_res; TOL: 0.05 ohm; VER: 1; XY: (-8300,5750)
R489 = R#1: ASSEMBLY: USBC; CDS_LIB: discrete; CDS_PART_NAME: R_0402-0OHM,0.05 OHM,62.5MW,195-2655-000; CDS_PHYS_PART_NAME: R_0402-0OHM,0.05 OHM,62.5MW,195-2655-000-0OHM,195-2655-000; CDS_SEC: 1; CHIPS_PART_NAME: R; DEVICE_TYPENAME: R_0402-0OHM005OHM625MW195-2655-000-0OHM195-2655-000; DRAWING: @P3768_A04_LIB.P3768_A04(SCH_1):PAGE13; MAX_WATTAGE: 62.5mW; NV_PN: 195-2655-000; PATH: I419; PHYS_PAGE: 13; ROT: 0; SEC: 1; SIGNAL_MODEL: nv_res; TOL: 0.05 ohm; VER: 1; XY: (-8300,5600)
R490 = R#1: ASSEMBLY: USBC; CDS_LIB: discrete; CDS_PART_NAME: R_0402-0OHM,0.05 OHM,62.5MW,195-2655-000; CDS_PHYS_PART_NAME: R_0402-0OHM,0.05 OHM,62.5MW,195-2655-000-0OHM,195-2655-000; CDS_SEC: 1; CHIPS_PART_NAME: R; DEVICE_TYPENAME: R_0402-0OHM005OHM625MW195-2655-000-0OHM195-2655-000; DRAWING: @P3768_A04_LIB.P3768_A04(SCH_1):PAGE13; MAX_WATTAGE: 62.5mW; NV_PN: 195-2655-000; PATH: I416; PHYS_PAGE: 13; ROT: 0; SEC: 1; SIGNAL_MODEL: nv_res; TOL: 0.05 ohm; VER: 1; XY: (-5600,5750)
R491 = R: ASSEMBLY: USBC; CDS_LIB: discrete; CDS_PART_NAME: R_0402-10K,5 %,62.5MW,195-0486-000; CDS_PHYS_PART_NAME: R_0402-10K,5 %,62.5MW,195-0486-000-10K,195-0486-000; CDS_SEC: 1; DEVICE_TYPENAME: R_0402-10K5625MW195-0486-000-10K195-0486-000; DRAWING: @P3768_A04_LIB.P3768_A04(SCH_1):PAGE13; MAX_WATTAGE: 62.5mW; NV_PN: 195-0486-000; PATH: I430; PHYS_PAGE: 13; PSPICETEMPLATE: X^@REFDES  %1    %2   @NV_PN; ROT: 0; SEC: 1; SIGNAL_MODEL: nv_res; TOL: 5 %; VER: 2; XY: (-5250,6050)
R492 = R: ASSEMBLY: USBC; CDS_LIB: discrete; CDS_PART_NAME: R_0402-10K,5 %,62.5MW,195-0486-000; CDS_PHYS_PART_NAME: R_0402-10K,5 %,62.5MW,195-0486-000-10K,195-0486-000; CDS_SEC: 1; DEVICE_TYPENAME: R_0402-10K5625MW195-0486-000-10K195-0486-000; DRAWING: @P3768_A04_LIB.P3768_A04(SCH_1):PAGE13; MAX_WATTAGE: 62.5mW; NV_PN: 195-0486-000; PATH: I427; PHYS_PAGE: 13; PSPICETEMPLATE: X^@REFDES  %1    %2   @NV_PN; ROT: 0; SEC: 1; SIGNAL_MODEL: nv_res; TOL: 5 %; VER: 2; XY: (-4350,6300)
R493 = R#1: ASSEMBLY: USBC; CDS_LIB: discrete; CDS_PART_NAME: R_0402-0OHM,0.05 OHM,62.5MW,195-2655-000; CDS_PHYS_PART_NAME: R_0402-0OHM,0.05 OHM,62.5MW,195-2655-000-0OHM,195-2655-000; CDS_SEC: 1; CHIPS_PART_NAME: R; DEVICE_TYPENAME: R_0402-0OHM005OHM625MW195-2655-000-0OHM195-2655-000; DRAWING: @P3768_A04_LIB.P3768_A04(SCH_1):PAGE13; MAX_WATTAGE: 62.5mW; NV_PN: 195-2655-000; PATH: I426; PHYS_PAGE: 13; ROT: 0; SEC: 1; SIGNAL_MODEL: nv_res; TOL: 0.05 ohm; VER: 1; XY: (-3550,6000)
R494 = R#1: ASSEMBLY: USBC; CDS_LIB: discrete; CDS_PART_NAME: R_0402-2M,5 %,62.5MW,195-0538-000; CDS_PHYS_PART_NAME: R_0402-2M,5 %,62.5MW,195-0538-000-195-0538-000,2M; CDS_SEC: 1; CHIPS_PART_NAME: R; DEVICE_TYPENAME: R_0402-2M5625MW195-0538-000-195-0538-0002M; DRAWING: @P3768_A04_LIB.P3768_A04(SCH_1):PAGE13; MAX_WATTAGE: 62.5mW; NV_PN: 195-0538-000; PATH: I397; PHYS_PAGE: 13; ROT: 0; SEC: 1; SIGNAL_MODEL: nv_res; SKU: DNI; TOL: 5 %; VER: 1; XY: (-3000,3550)
R495 = R#1: ASSEMBLY: USBC; CDS_LIB: discrete; CDS_PART_NAME: R_0402-2M,5 %,62.5MW,195-0538-000; CDS_PHYS_PART_NAME: R_0402-2M,5 %,62.5MW,195-0538-000-195-0538-000,2M; CDS_SEC: 1; CHIPS_PART_NAME: R; DEVICE_TYPENAME: R_0402-2M5625MW195-0538-000-195-0538-0002M; DRAWING: @P3768_A04_LIB.P3768_A04(SCH_1):PAGE13; MAX_WATTAGE: 62.5mW; NV_PN: 195-0538-000; PATH: I394; PHYS_PAGE: 13; ROT: 0; SEC: 1; SIGNAL_MODEL: nv_res; SKU: DNI; TOL: 5 %; VER: 1; XY: (-3000,3450)
R498 = R#1: ASSEMBLY: USBC; CDS_LIB: discrete; CDS_PART_NAME: R_0402-0OHM,0.05 OHM,62.5MW,195-2655-000; CDS_PHYS_PART_NAME: R_0402-0OHM,0.05 OHM,62.5MW,195-2655-000-0OHM,195-2655-000; CDS_SEC: 1; CHIPS_PART_NAME: R; DEVICE_TYPENAME: R_0402-0OHM005OHM625MW195-2655-000-0OHM195-2655-000; DRAWING: @P3768_A04_LIB.P3768_A04(SCH_1):PAGE13; MAX_WATTAGE: 62.5mW; NV_PN: 195-2655-000; PATH: I454; PHYS_PAGE: 13; PLACEMENT_NOTE: CoLayout with L10; ROT: 0; SEC: 1; SIGNAL_MODEL: DEFAULT_RESISTOR_0.001OHM_2_1; TOL: 0.05 ohm; VER: 1; XY: (-5650,2750)
R499 = R#1: ASSEMBLY: USBC; CDS_LIB: discrete; CDS_PART_NAME: R_0402-0OHM,0.05 OHM,62.5MW,195-2655-000; CDS_PHYS_PART_NAME: R_0402-0OHM,0.05 OHM,62.5MW,195-2655-000-0OHM,195-2655-000; CDS_SEC: 1; CHIPS_PART_NAME: R; DEVICE_TYPENAME: R_0402-0OHM005OHM625MW195-2655-000-0OHM195-2655-000; DRAWING: @P3768_A04_LIB.P3768_A04(SCH_1):PAGE13; MAX_WATTAGE: 62.5mW; NV_PN: 195-2655-000; PATH: I455; PHYS_PAGE: 13; PLACEMENT_NOTE: CoLayout with L10; ROT: 0; SEC: 1; SIGNAL_MODEL: DEFAULT_RESISTOR_0.001OHM_2_1; TOL: 0.05 ohm; VER: 1; XY: (-5650,2450)
U37 = U_MUX_PCIE: ASSEMBLY: USBC; CDS_LIB: logic; CDS_PART_NAME: U_MUX_PCIE_TQFN_20_R-PI3DBS12212AZBSEX_EOL,OTHER,115-2489-000; CDS_PHYS_PART_NAME: U_MUX_PCIE_TQFN_20_R-PI3DBS12212AZBSEX_EOL,OTHER,115-2489-000-115-2489-000; CDS_SEC: 1; DEVICE_TYPENAME: U_MUX_PCIE_TQFN_20_R-PI3DBS12212AZBSEX_EOLOTHER115-2489-000-115-2489-000; DRAWING: @P3768_A04_LIB.P3768_A04(SCH_1):PAGE13; FUNCTION: Other; NV_NAME: PI3DBS12212AZBSEX_EOL; NV_PN: 115-2489-000; PACK_TYPE: TQFN_20_R; PATH: I350; PHYS_PAGE: 13; ROT: 0; SEC: 1; VER: 1; XY: (-8050,3150)
U54 = U_USB_FUSB301: ASSEMBLY: USBC; CDS_LIB: digital; CDS_PART_NAME: U_USB_FUSB301_QFN10-FUSB301TMX,USB,115-2791-000; CDS_PHYS_PART_NAME: U_USB_FUSB301_QFN10-FUSB301TMX,USB,115-2791-000-115-2791-000; CDS_SEC: 1; DEVICE_TYPENAME: U_USB_FUSB301_QFN10-FUSB301TMXUSB115-2791-000-115-2791-000; DRAWING: @P3768_A04_LIB.P3768_A04(SCH_1):PAGE13; NV_NAME: FUSB301TMX; NV_PN: 115-2791-000; PACK_TYPE: QFN10; PATH: I333; PHYS_PAGE: 13; ROT: 0; SEC: 1; SEC_TYPE: QFN10; TYPE: USB; VER: 1; XY: (-7200,5900)
U55 = U_SW_LOAD: ASSEMBLY: USBC; CDS_LIB: analog; CDS_PART_NAME: U_SW_LOAD_SOT23_5B-AP22811AW5-7,0MV..5.5V,2.7V..5.5V,9999A,SWITCH,115-2766-000; CDS_PHYS_PART_NAME: U_SW_LOAD_SOT23_5B-AP22811AW5-7,0MV..5.5V,2.7V..5.5V,9999A,SWITCH,115-2766-000-115-2766-000; CDS_SEC: 1; DEVICE_TYPENAME: U_SW_LOAD_SOT23_5B-AP22811AW5-70MV55V27V55V9999ASWITCH115-2766-000-115-2766-000; DRAWING: @P3768_A04_LIB.P3768_A04(SCH_1):PAGE13; MAX_CURRENT: 9999A; MAX_VOLTAGE: 2.7V..5.5V; NV_NAME: AP22811AW5-7; NV_PN: 115-2766-000; OUTPUT_VOLTAGE: 0mV..5.5V; PACK_TYPE: SOT23_5B; PATH: I469; PHYS_PAGE: 13; ROT: 0; SEC: 1; TYPE: Switch; VER: 7; XY: (-2450,6000)

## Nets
GND: C39.2 C157.2 C377.2 C378.2 C379.2 C380.2 C381.2 C382.2 C383.2 C389.2 C390.2 D5.2 D67.3(GND1) D68.3(GND1) D69.3(GND1) D73.A J5.25(SH1) J5.26(SH2) J5.27(SH3) J5.28(SH4) J5.A1(GND1) J5.A12(GND2) J5.B1(GND3) J5.B12(GND4) Q54.2(S) R485.2 R486.2 R494.1 R495.1 U37.5(GND_1) U37.11(GND_2) U37.20(GND_3) U37.21(GND_4) U54.4(GND) U55.2(GND) ; also on sheet 1 2 3 4 5 6 7 8 9 10 11 13 14 15 16 17 18 19 21 25
VDD_1V8: R483.1 ; also on sheet 1 2 3 5 8 14 19 21
VDD_3V3_SYS: C377.1 C378.1 C379.1 C380.1 R484.1 R491.1 R492.1 U37.1(VDD) U37.6(VDD_2) U37.10(VDD_3) U54.5(VDD) ; also on sheet 1 2 3 4 5 6 7 8 11 14 15 19 20 21
VDD_5V_SYS: C389.1 U55.5(IN) ; also on sheet 1 2 8 9 10 11 13 14 15 16 17 21
FUSB_ID: R490.1 U54.3(ID)
FUSB_ID_R: Q54.1(G) R490.2 R491.2
FUSB_INT_N: R489.2 U54.10(INT_N)
FUSB_SCL: R487.2 U54.2(SCL)
FUSB_SDA: R488.2 U54.1(SDA)
ID_I2C_SCL: R487.1 ; also on sheet 2 21
ID_I2C_SDA: R488.1 ; also on sheet 2 21
SNN_USBC_OCP_N: U55.3(OC*)
USB0_AP_N: L48.1 R498.1 ; also on sheet 20
USB0_AP_P: L48.2 R499.1 ; also on sheet 20
USB0_CON_N: D67.1(1A) D67.10(1B) J5.A7(D1_N) J5.B7(D2_N) L48.4 R498.2
USB0_CON_P: D67.2(2A) D67.9(2B) J5.A6(D1_P) J5.B6(D2_P) L48.3 R499.2
USB0_VBUS_DET*: R483.2 R489.1 ; also on sheet 20
USBC_CC1: C382.1 D67.4(3A) D67.7(3B) J5.A5(CC1) U54.6(CC1)
USBC_CC2: C383.1 D67.5(4A) D67.6(4B) J5.B5(CC2) U54.7(CC2)
USBC_LSW_EN: R493.2 U55.4(EN)
USBC_LSW_EN_R: Q54.3(D) R492.2 R493.1
USBC_MUX_OE_N: R486.1 U37.2(PD)
USBC_MUX_SEL: R482.1 U54.9(SS_SW)
USBC_MUX_SEL_R: R482.2 R484.2 R485.1 U37.9(SEL)
USBC_RX1_N: D68.2(2A) D68.9(2B) J5.B10(SSRX1_N) U37.18(B0N)
USBC_RX1_P: D68.1(1A) D68.10(1B) J5.B11(SSRX1_P) U37.19(B0P)
USBC_RX2_N: D69.2(2A) D69.9(2B) J5.A10(SSRX2_N) U37.14(C0N)
USBC_RX2_P: D69.1(1A) D69.10(1B) J5.A11(SSRX2_P) U37.15(C0P)
USBC_SBU1: J5.A8(SBU1) R494.2
USBC_SBU2: J5.B8(SBU2) R495.2
USBC_TX1_C_N: C386.1 U37.16(B1N)
USBC_TX1_C_P: C384.1 U37.17(B1P)
USBC_TX1_N: C386.2 D68.5(4A) D68.6(4B) J5.A3(SSTX1_N)
USBC_TX1_P: C384.2 D68.4(3A) D68.7(3B) J5.A2(SSTX1_P)
USBC_TX2_C_N: C388.1 U37.12(C1N)
USBC_TX2_C_P: C385.1 U37.13(C1P)
USBC_TX2_N: C388.2 D69.5(4A) D69.6(4B) J5.B3(SSTX2_N)
USBC_TX2_P: C385.2 D69.4(3A) D69.7(3B) J5.B2(SSTX2_P)
USBC_VBUS: C39.1 C157.1 C381.1 C390.1 D5.1 D73.K J5.A4(VBUS1) J5.A9(VBUS2) J5.B4(VBUS3) J5.B9(VBUS4) U54.8(VBUS) U55.1(OUT)
USBSS1_RX_N: U37.4(A0N) ; also on sheet 19
USBSS1_RX_P: U37.3(A0P) ; also on sheet 19
USBSS1_TX_N: U37.8(A1N) ; also on sheet 19
USBSS1_TX_P: U37.7(A1P) ; also on sheet 19

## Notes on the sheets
sheet 12
- A
- B
- C
- D
- E
- F
- G
- H
- USB-C (Recovery Port)
- 1
- 1
- VIH>1.5V
- ID
- SINK
- VIL<0.5V
- Hi-Z (default)
- Not Detected
- Low
- Detected
- I2CADDR:7'h25
- 2
- 2
- PCB CO-LAYOUT
- 0.1uF close to connector
- 3
- 3
- PCB CO-LAYOUT
- 0: A=>B
- 1: A=>C
- 4
- 4
- 5
- 5
- NVIDIA CORPORATION
- 2701 SAN TOMAS EXPRESSWAY
- SANTA CLARA, CA 95050, USA
- ASSEMBLY
- <ASSEMBLY_DESCRIPTION>
- PAGE DETAIL
- USB Type C
- 600-13768-BASE-400
- NV_PN
- ALL NVIDIA DESIGN SPECIFICATIONS, REFERENCE SPECIFICATIONS, REFERENCE BOARDS, FILES, DRAWINGS, DIAGNOSTICS, LISTS AND OTHER DOCUMENTS OR INFORMATION (TOGETHER AND SEPARATELY, 'MATERIALS') ARE BEING PROVIDED 'AS IS'. THE MATERIALS MAY
- P3768-A04
- 13 OF 25
- CONTAIN KNOWN AND UNKNOWN VIOLATIONS OR DEVIATIONS OF INDUSTRY STANDARDS AND SPECIFICATIONS. NVIDIA MAKES NO WARRANTIES, EXPRESSED, IMPLIED, STATUTORY OR OTHERWISE WITH RESPECT TO THE MATERIALS OR OTHERWISE, AND EXPRESSLY DISCLAIMS ALL
- PCB REV
- PAGE
- IMPLIED WARRANTIES INCLUDING, WITHOUT LIMITATION, THE WARRANTIES OF DESIGN, OF NONINFRINGEMENT, MERCHANTABILITY OR FITNESS FOR A PARTICULAR PURPOSE, OR ARISING FROM A COURSE OF DEALING, TRADE USAGE, TRADE PRACTICE, OR INDUSTRY STANDARDS.
- BOM REV
- A
- DATE
- 27-FEB-2023
- A
- B
- C
- D
- E
- F
- G
- H
